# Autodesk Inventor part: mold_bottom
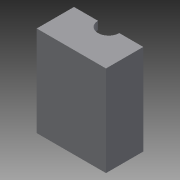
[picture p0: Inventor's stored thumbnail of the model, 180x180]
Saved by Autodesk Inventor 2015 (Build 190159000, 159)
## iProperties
Created: 2015-04
Part Number: mold_bottom
Material: Generic
Document SubType Name: Modeling
Designer: sungeun
Density: 1 g/cm^3
Appearance: Default
Author: sungeun
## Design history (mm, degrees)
sketch "Sketch1"
  geometry: L1 (-65, -35)-(65, -35); L2 (65, -35)-(65, 35); L3 (65, 35)-(-65, 35); L4 (-65, 35)-(-65, -35); L5 (-65, -35)-(65, 35); L6 (65, -35)-(-65, 35); 1 further point
  constraints: 12 end point, 2 midpoint, 2 parallel, 1 horizontal, 1 perpendicular
  dimensions: "d0" = 130 distance of L2.end L3.end; "d1" = 70 distance of L1.end L2.end
extrude "Extrusion1" new body sketch "Sketch1" stored distance "d2" = 170; taper "d3" = 0 deg
sketch "Sketch2" dims "d20" = 75, "d21" = 55
  geometry: L1 (65, 160)-(65, 10); 2 further points; 1 other entity
  constraints: 2 end point, 1 coincident, 1 vertical, 4 other
  dimensions: "d27" = 150 distance of L1.start L1.end
sketch "Sketch3"
  geometry: L1 (130, 170)-(130, 0) reference; L2 (115, 147.5)-(115, 162.5); A1 r 7.5 centre (115, 155) between (115, 147.5) and (115, 162.5); 1 further point
  constraints: 2 end point, 2 point on circle, 1 centre point, 1 vertical
  dimensions: "d6" = 70 vertical distance of point (65, 85) A1.centre; "d7" = 50 horizontal distance of point (65, 85) A1.centre; "d8" = 15 diameter of A1; "d9" = 15 distance of L2.start L2.end
revolve "Revolution2" sketch "Sketch3" stored, may be unused: angle "d10" = 90 deg
pattern_linear "Rectangular Pattern1" dims "d13" = 135
revolve "Revolution3" stored, may be unused: angle "d23" = 90 deg
sketch "Sketch5"
  geometry: L1 (-20, 35)-(20, 35); A1 r 20 centre (0, 35) between (-20, 35) and (20, 35); 3 further points
  constraints: 3 point on circle, 2 end point, 2 vertical alignment, 1 centre point, 1 coincident
  dimensions: "d29" = 20 radius of A1
extrude "Extrusion3" cut sketch "Sketch5" distance "d25" = 165; taper "d26" = 0 deg
body "Solid1"
